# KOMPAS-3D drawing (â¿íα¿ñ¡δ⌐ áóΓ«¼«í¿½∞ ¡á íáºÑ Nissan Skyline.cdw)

Referenced files: Общий вид Скайлайн.cdw
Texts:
  ДР.2011.40.461.806.10.37.004.000.000
  Гибридный автомобиль на базе Nissan Skyline
  Дитковский
  Дитковский Р.С.
  Шевчук В.П.
  Котовсков А.В.
  Ляшенко М.В.
Dimensions and other numbers on the sheet: 2665; 4600; 140; 130; 1360; 1480; 1785; 1490; 1:10; 1; 9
